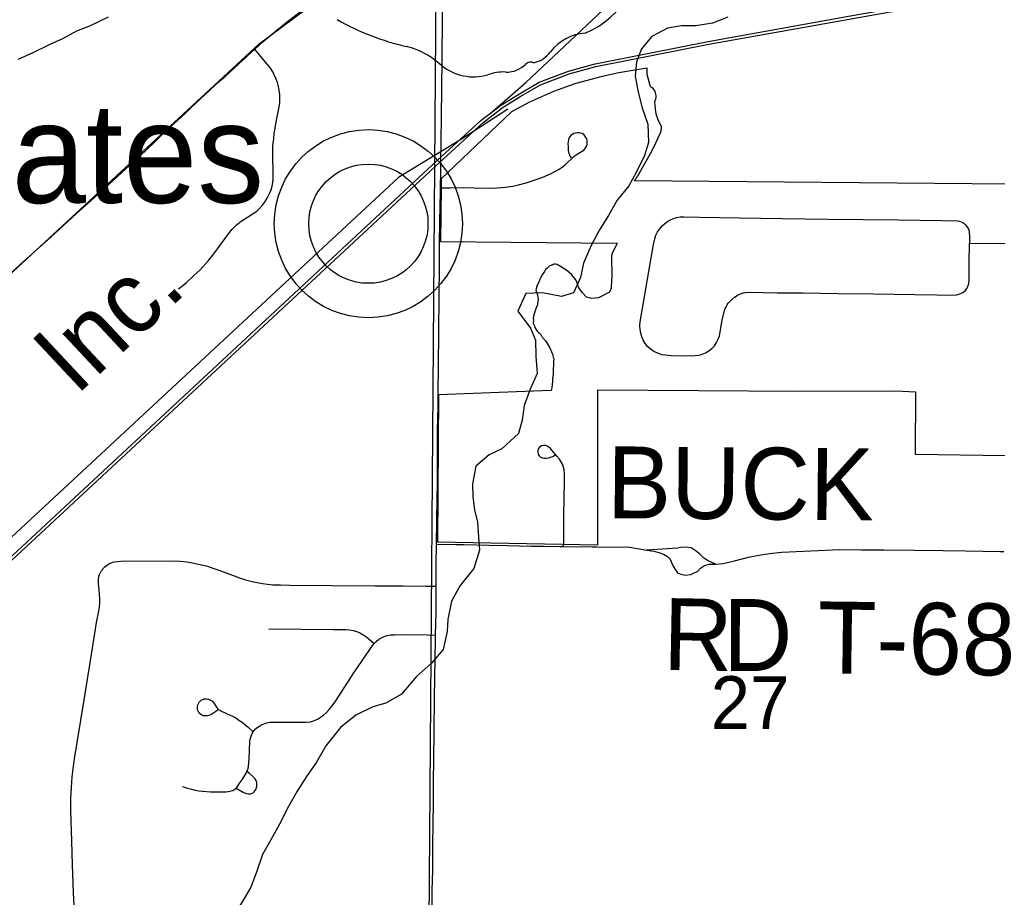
# Model space of a CAD drawing. Extents: x 0 to 34, y 0 to 22.
# Drawn here: x 5.674 to 6.448, y 19.121 to 19.815 of the extents above; entities that cross this region are included whole.
import ezdxf

# ---------------------------------------------------------------- set-up
doc = ezdxf.new("R2010")
doc.units = 0
for name, color, linetype in [('GM_X_City_Street', 7, 'Continuous'), ('GM_X_Corporation', 7, 'Continuous'), ('GM_X_Major_River', 7, 'Continuous'), ('GM_X_Minor_River', 7, 'Continuous'), ('GM_X_Rail_Line', 7, 'Continuous'), ('GM_X_Rail_Line_Text', 7, 'Continuous'), ('GM_X_Section_Text', 7, 'Continuous'), ('GM_X_State_Route', 7, 'Continuous'), ('GM_X_State_Shield', 7, 'Continuous'), ('GM_X_Township_Road', 7, 'Continuous'), ('GM_X_Township_Road_Text', 7, 'Continuous'), ('GM_X_Unincorporated', 7, 'Continuous'), ('GM_X_Unincorporated_Location', 7, 'Continuous'), ('GM_X_Unincorporated_Text', 7, 'Continuous')]:
    doc.layers.add(name, color=color, linetype=linetype)

msp = doc.modelspace()

# ---------------------------------------------------------------- linework, layer by layer
at = {"layer": 'GM_X_City_Street'}
for points in [[(6.0071, 19.68221), (6.01468, 19.68223), (6.02558, 19.68226), (6.03339, 19.68224), (6.04583, 19.68197), (6.052, 19.68215), (6.05816, 19.68266), (6.06428, 19.68351), (6.0688, 19.68441), (6.07476, 19.68603), (6.0821, 19.68847), (6.08813, 19.69067), (6.09451, 19.69333), (6.10088, 19.69696), (6.10327, 19.69856), (6.10576, 19.70044), (6.11251, 19.70691), (6.11378, 19.70795), (6.11515, 19.70885), (6.11923, 19.71112), (6.12039, 19.71197), (6.12138, 19.71295), (6.12218, 19.71408), (6.12277, 19.71533), (6.12313, 19.71666), (6.12324, 19.71804), (6.12311, 19.71942), (6.12273, 19.72077), (6.12214, 19.72205), (6.12135, 19.72322), (6.1204, 19.72421), (6.11929, 19.72497), (6.11805, 19.72541), (6.1167, 19.72557), (6.11522, 19.72556), (6.11378, 19.72539), (6.11246, 19.72502), (6.11125, 19.72441), (6.11021, 19.72357), (6.10933, 19.72252), (6.10867, 19.72131), (6.10824, 19.71998), (6.10805, 19.71858), (6.10789, 19.71681), (6.10796, 19.71477), (6.10806, 19.71307), (6.10818, 19.71169), (6.10864, 19.70936), (6.10903, 19.70818), (6.10965, 19.70685), (6.11039, 19.70579)], [(6.1755, 19.55305), (6.17305, 19.55475), (6.17087, 19.55676), (6.169, 19.55905), (6.1675, 19.56161), (6.16635, 19.56437), (6.16554, 19.56725), (6.16502, 19.5702), (6.16489, 19.57318), (6.16512, 19.57617), (6.16908, 19.59907), (6.17185, 19.61597), (6.17562, 19.63735), (6.1766, 19.6418), (6.17753, 19.64464), (6.1788, 19.64729), (6.18048, 19.64977), (6.18244, 19.65205), (6.18574, 19.65509)], [(6.18574, 19.65509), (6.18819, 19.65657), (6.19094, 19.65773), (6.19381, 19.65858), (6.19678, 19.65908), (6.19981, 19.65927), (6.21219, 19.65903), (6.24336, 19.65837), (6.27762, 19.65796), (6.31344, 19.65744), (6.36951, 19.65671), (6.40377, 19.65629), (6.41616, 19.65593), (6.41759, 19.65572), (6.41895, 19.65533), (6.42021, 19.65475), (6.42137, 19.65396), (6.4224, 19.65299), (6.4233, 19.65187), (6.42406, 19.65064), (6.4247, 19.64932), (6.42523, 19.64794), (6.42567, 19.64279), (6.42552, 19.6381), (6.46088, 19.63839)], [(6.1755, 19.55305), (6.17915, 19.55129), (6.18202, 19.55045), (6.185, 19.54996), (6.18959, 19.54958), (6.19889, 19.54938), (6.2082, 19.5495), (6.2112, 19.54978), (6.21264, 19.55008), (6.21405, 19.5505), (6.21674, 19.55172), (6.2193, 19.5533), (6.22169, 19.55514), (6.22375, 19.55726), (6.22547, 19.55969), (6.22679, 19.56235), (6.22767, 19.56517), (6.22996, 19.57741), (6.23177, 19.58505), (6.23231, 19.58662), (6.23301, 19.58812), (6.23382, 19.58953), (6.23475, 19.59088), (6.23691, 19.59332), (6.23938, 19.59541), (6.24209, 19.59718), (6.24355, 19.59793), (6.24507, 19.59855), (6.24665, 19.59902), (6.24828, 19.59932), (6.2515, 19.59952), (6.26245, 19.59931), (6.27333, 19.599), (6.29358, 19.59896), (6.32162, 19.59856), (6.34966, 19.59826), (6.38239, 19.59773), (6.3997, 19.59745), (6.41039, 19.59729), (6.41493, 19.59752), (6.41638, 19.59778), (6.41778, 19.59819), (6.41913, 19.59873), (6.4204, 19.59943), (6.42154, 19.60028), (6.42255, 19.60128), (6.42339, 19.60241), (6.42407, 19.60366), (6.42459, 19.605), (6.42493, 19.6064), (6.42517, 19.60937), (6.42534, 19.62305), (6.42552, 19.6381)], [(6.10452, 19.3985), (6.10454, 19.40149), (6.10457, 19.40692), (6.10465, 19.42299), (6.10512, 19.44961), (6.10512, 19.45587), (6.10481, 19.45899), (6.10412, 19.46204), (6.10357, 19.46351), (6.10288, 19.46491), (6.10206, 19.46623), (6.1011, 19.46748), (6.09905, 19.46984), (6.09401, 19.47586), (6.09288, 19.47695), (6.09159, 19.4778), (6.09012, 19.47829), (6.08856, 19.47836), (6.08704, 19.47801), (6.08568, 19.47723), (6.08464, 19.47609), (6.08404, 19.47467), (6.08397, 19.47311), (6.08436, 19.47159), (6.08517, 19.47025), (6.08632, 19.4692), (6.08775, 19.46857), (6.08929, 19.46833), (6.09086, 19.46828), (6.0924, 19.46851), (6.09424, 19.469), (6.09585, 19.46965), (6.09762, 19.47071)]]:
    msp.add_lwpolyline(points, dxfattribs=at)
at = {"layer": 'GM_X_Corporation'}
msp.add_lwpolyline([(6.51238, 19.90438), (6.50454, 18.87812), (5.99643, 18.88937), (6.00425, 19.91036)], close=True, dxfattribs=at)
msp.add_lwpolyline([(6.4572, 19.685), (6.16051, 19.68759), (6.16083, 19.68838), (6.16145, 19.68903), (6.16175, 19.6894), (6.16244, 19.69072), (6.16314, 19.69161), (6.17329, 19.70935), (6.17613, 19.71492), (6.18098, 19.72499), (6.18139, 19.72653), (6.18177, 19.72724), (6.18187, 19.72915), (6.18184, 19.73042), (6.17932, 19.73595), (6.17798, 19.73953), (6.17736, 19.74213), (6.17671, 19.75011), (6.17706, 19.75174), (6.17738, 19.75225), (6.17763, 19.75317), (6.17776, 19.75511), (6.17678, 19.75844), (6.17615, 19.7597), (6.17534, 19.7606), (6.17406, 19.76149), (6.17323, 19.76235), (6.17283, 19.76309), (6.17048, 19.77176), (6.17048, 19.77666), (6.14818, 19.77306), (6.13503, 19.77029), (6.11428, 19.76453), (6.09655, 19.75819), (6.07741, 19.74977), (6.06327, 19.74233), (6.00764, 19.68915), (6.00757, 19.68273), (6.00709, 19.63957), (6.11861, 19.63869), (6.14691, 19.63846), (6.14422, 19.63279), (6.14273, 19.63003), (6.14234, 19.62809), (6.14271, 19.61149), (6.14234, 19.60905), (6.14219, 19.60275), (6.14065, 19.5995), (6.132, 19.5951), (6.12683, 19.59467), (6.12469, 19.59507), (6.12253, 19.59568), (6.11931, 19.59901), (6.11805, 19.60102), (6.11634, 19.60365), (6.1158, 19.60555), (6.11414, 19.60936), (6.11108, 19.61343), (6.10671, 19.61707), (6.09926, 19.62158), (6.09812, 19.62188), (6.09682, 19.62172), (6.09574, 19.62125), (6.09528, 19.62124), (6.09504, 19.62101), (6.09348, 19.62039), (6.09317, 19.62018), (6.09266, 19.61962), (6.09112, 19.61825), (6.09026, 19.61746), (6.08929, 19.61609), (6.08749, 19.61331), (6.08674, 19.61202), (6.0862, 19.61082), (6.08597, 19.61037), (6.08578, 19.60964), (6.08477, 19.6074), (6.08368, 19.60519), (6.08348, 19.60501), (6.08313, 19.60402), (6.08294, 19.6031), (6.08275, 19.60216), (6.08263, 19.60124), (6.08266, 19.60066), (6.08283, 19.60011), (6.08358, 19.59836), (6.08385, 19.59669), (6.08434, 19.59466), (6.08439, 19.59429), (6.08422, 19.59201), (6.08393, 19.59016), (6.08375, 19.5896), (6.08273, 19.58735), (6.08095, 19.58178), (6.08049, 19.57917), (6.08056, 19.57784), (6.08052, 19.57519), (6.08091, 19.57393), (6.08137, 19.57308), (6.08163, 19.57207), (6.08172, 19.5718), (6.08298, 19.56969), (6.08388, 19.56848), (6.08452, 19.56779), (6.08544, 19.56712), (6.08587, 19.56674), (6.08634, 19.56613), (6.08715, 19.56465), (6.08749, 19.56419), (6.08772, 19.56388), (6.08798, 19.5636), (6.08874, 19.56271), (6.08905, 19.56228), (6.08931, 19.56201), (6.08948, 19.56189), (6.08962, 19.56176), (6.09013, 19.56111), (6.09077, 19.56028), (6.0913, 19.55947), (6.09163, 19.5588), (6.0917, 19.55862), (6.09186, 19.55838), (6.09251, 19.55756), (6.093, 19.55675), (6.09414, 19.55416), (6.09561, 19.55067), (6.0959, 19.54938), (6.09633, 19.54832), (6.09645, 19.54757), (6.09668, 19.54674), (6.09645, 19.54524), (6.09631, 19.5352), (6.09599, 19.53266), (6.09581, 19.53125), (6.09567, 19.52898), (6.09524, 19.52407), (6.09453, 19.52177), (6.00553, 19.51842), (6.00473, 19.40219), (6.13146, 19.39982), (6.13153, 19.52233), (6.29046, 19.52131), (6.36736, 19.52147), (6.38296, 19.52085), (6.38257, 19.47159), (6.4539, 19.47047)], dxfattribs=at)
at = {"layer": 'GM_X_Major_River'}
msp.add_lwpolyline([(5.67296, 19.78399), (5.68429, 19.78888), (5.69843, 19.79584), (5.70831, 19.80027), (5.71934, 19.80621), (5.7296, 19.81026), (5.74459, 19.81733)], dxfattribs=at)
at = {"layer": 'GM_X_Minor_River'}
for points in [[(6.2345, 19.81701), (6.22235, 19.81223), (6.2091, 19.81012), (6.19777, 19.81026), (6.18679, 19.8085), (6.17423, 19.80182), (6.16617, 19.79206), (6.16226, 19.78186), (6.16098, 19.77011), (6.16383, 19.75679), (6.1667, 19.74537), (6.17106, 19.73242), (6.17163, 19.71799), (6.16847, 19.70778), (6.16187, 19.6942), (6.15607, 19.68365), (6.14686, 19.67238), (6.1399, 19.66032), (6.13295, 19.64902), (6.12637, 19.63658), (6.12014, 19.62262), (6.11772, 19.61126), (6.11228, 19.59919), (6.1028, 19.59627), (6.08772, 19.59912), (6.07449, 19.59852), (6.06826, 19.58456), (6.07829, 19.57115), (6.08232, 19.56161), (6.08254, 19.54909), (6.08349, 19.53541), (6.07804, 19.52295), (6.07334, 19.51011), (6.07167, 19.49837), (6.06889, 19.48778), (6.05551, 19.4758), (6.04563, 19.47099), (6.03493, 19.46202), (6.03248, 19.44801), (6.03273, 19.43775), (6.0341, 19.42749), (6.03624, 19.4176), (6.03722, 19.40582), (6.03784, 19.39556), (6.0335, 19.3812), (6.02275, 19.36767), (6.01578, 19.35523), (6.01295, 19.34085), (6.01245, 19.33137), (6.00924, 19.31698), (6.00003, 19.30609), (5.98819, 19.29562), (5.97629, 19.28172), (5.96373, 19.27467), (5.9535, 19.27176), (5.94019, 19.2651), (5.92797, 19.25538), (5.91645, 19.24073), (5.9091, 19.22792), (5.90102, 19.21663), (5.89369, 19.20496), (5.88674, 19.1929), (5.87975, 19.17894)], [(5.87975, 19.17894), (5.87279, 19.16651), (5.86622, 19.15483), (5.8615, 19.14084), (5.85719, 19.12913), (5.84986, 19.11708), (5.84023, 19.10278), (5.82763, 19.09231), (5.81088, 19.08303), (5.79986, 19.07786), (5.78959, 19.07267), (5.77894, 19.06673), (5.76907, 19.06344), (5.75694, 19.0598), (5.74441, 19.0554), (5.73301, 19.04985), (5.72349, 19.04466), (5.71465, 19.033), (5.70465, 19.01871)]]:
    msp.add_lwpolyline(points, dxfattribs=at)
at = {"layer": 'GM_X_Rail_Line'}
msp.add_line((6.06042, 19.74445), (6.02958, 19.7244), dxfattribs=at)
for points in [[(4.78429, 18.80343), (5.20213, 19.1854), (5.56639, 19.5213), (5.86365, 19.79605), (5.94571, 19.8572), (6.00433, 19.89992), (6.77122, 20.65037), (6.78738, 20.68459), (6.84059, 20.85665), (6.88559, 20.9)], [(6.04603, 19.74071), (6.07463, 19.76544), (6.4431, 20.11209)], [(6.0391, 19.7355), (6.05467, 19.74722), (6.06953, 19.75648), (6.08509, 19.76562), (6.10827, 19.77436), (6.12947, 19.7803), (6.21883, 19.79798), (6.32982, 19.81787), (6.51134, 19.85016), (6.6502, 19.87532), (6.69488, 19.88232), (6.73475, 19.88693), (6.77076, 19.89004), (6.82866, 19.89259), (6.91252, 19.89191), (7.71042, 19.87786)], [(6.04051, 19.73365), (6.056, 19.74531), (6.07074, 19.7545), (6.0861, 19.76352), (6.109, 19.77215), (6.13002, 19.77804), (6.21926, 19.7957), (6.33023, 19.81559), (6.51176, 19.84787), (6.65059, 19.87303), (6.69519, 19.88002), (6.73499, 19.88462), (6.77091, 19.88772), (6.82871, 19.89027), (6.91249, 19.88959), (7.71038, 19.87554)], [(4.0369, 17.87629), (4.0405, 17.87963), (4.10582, 17.94022), (4.26502, 18.087), (4.55609, 18.35576), (4.76707, 18.55171), (4.9213, 18.69505), (5.34845, 19.09084), (6.00629, 19.70228), (6.04051, 19.73365)], [(4.26344, 18.0887), (4.5545, 18.35746), (4.76549, 18.55341), (4.91971, 18.69674), (5.34686, 19.09254), (6.00471, 19.70399), (6.03893, 19.73535)], [(6.02958, 19.7244), (6.02241, 19.71974), (5.97395, 19.69027), (5.5555, 19.30184), (5.32439, 19.08907), (5.10249, 18.8805), (5.04303, 18.84113), (4.98191, 18.81432), (4.92078, 18.80008), (4.84793, 18.79757), (4.78429, 18.80343)]]:
    msp.add_lwpolyline(points, dxfattribs=at)
at = {"layer": 'GM_X_State_Route'}
msp.add_lwpolyline([(5.66772, 19.61524), (5.67694, 19.62362), (5.69914, 19.6435), (5.71904, 19.66149), (5.73343, 19.67439), (5.74491, 19.68501), (5.75824, 19.69703), (5.77376, 19.71133), (5.78227, 19.71958), (5.78831, 19.72555), (5.79332, 19.73003), (5.80512, 19.74099), (5.80958, 19.74533), (5.82087, 19.756), (5.83239, 19.76635), (5.83702, 19.77046), (5.84391, 19.77672), (5.85077, 19.78303), (5.85761, 19.78938), (5.86024, 19.79178), (5.8668, 19.79776), (5.87624, 19.80587), (5.88609, 19.81358), (5.89713, 19.82218)], dxfattribs=at)
at = {"layer": 'GM_X_State_Shield'}
for centre, radius, start, end in [((6.09506, 19.86925), 0.06994, 292.30889, 8.98584), ((6.02504, 19.99079), 0.20192, 240.41292, 257.1985), ((6.12455, 19.76635), 0.0383, 94.40312, 142.57675), ((5.96484, 19.73263), 0.06318, 47.18416, 75.83597), ((6.07602, 19.80314), 0.0226, 282.87319, 323.27711), ((6.03317, 19.81), 0.04009, 230.70037, 286.29184), ((6.05926, 19.79501), 0.02136, 268.77702, 315.54927), ((6.07859, 19.77563), 0.00601, 65.75173, 132.64842), ((6.05633, 19.74081), 0.03294, 85.69512, 111.20995)]:
    msp.add_arc(centre, radius, start, end, dxfattribs=at)
at = {"layer": 'GM_X_Township_Road'}
msp.add_line((6.0071, 19.68221), (6.00741, 19.69531), dxfattribs=at)
for points in [[(6.00741, 19.69531), (6.00741, 19.70251), (6.00767, 19.71953), (6.00784, 19.73795), (6.00843, 19.78409), (6.00859, 19.81602), (6.00853, 19.8374), (6.0091, 19.86146), (6.00944, 19.88418), (6.00927, 19.88778), (6.00847, 19.89418), (6.00803, 19.89681), (6.00649, 19.90319)], [(5.79986, 19.60215), (5.80585, 19.60712), (5.81204, 19.61275), (5.817, 19.61734), (5.82346, 19.62456), (5.82778, 19.63), (5.8393, 19.64565), (5.8423, 19.64931), (5.84548, 19.6525), (5.84951, 19.65568), (5.85448, 19.65906), (5.86169, 19.66375), (5.86366, 19.66553), (5.866, 19.66825), (5.86778, 19.6705), (5.86918, 19.67257), (5.87059, 19.675), (5.87218, 19.67819), (5.87312, 19.68044), (5.87396, 19.68335), (5.87452, 19.68625), (5.8748, 19.68925), (5.8748, 19.6929), (5.8747, 19.69722), (5.87452, 19.70434), (5.87442, 19.70931), (5.8746, 19.71521), (5.87516, 19.72093), (5.87544, 19.72515), (5.87619, 19.72936), (5.87694, 19.73283), (5.87823, 19.7397), (5.87956, 19.74614), (5.87993, 19.74924), (5.88002, 19.75252), (5.87993, 19.7557), (5.87955, 19.75927), (5.87899, 19.76236), (5.87814, 19.76545), (5.87693, 19.76854), (5.87561, 19.77136), (5.87439, 19.77398), (5.87261, 19.77679), (5.86379, 19.78747), (5.86024, 19.79178)], [(6.00641, 19.63808), (6.00663, 19.65571), (6.00702, 19.679), (6.0071, 19.68221)], [(6.00535, 19.51719), (6.00544, 19.54426), (6.00578, 19.56496), (6.00603, 19.59882), (6.00641, 19.6171), (6.00638, 19.6265), (6.00641, 19.63808)], [(6.00398, 19.40044), (6.00423, 19.41849), (6.00448, 19.4363), (6.00474, 19.44875), (6.00473, 19.47603), (6.00472, 19.48848), (6.00496, 19.50135), (6.00516, 19.50755), (6.00535, 19.51719)], [(6.00362, 19.36707), (6.0037, 19.38386), (6.00398, 19.40044)], [(6.00398, 19.40044), (6.01951, 19.40008), (6.0253, 19.40009), (6.04568, 19.39962), (6.05981, 19.39929), (6.07874, 19.39885), (6.08869, 19.39878), (6.10177, 19.39853), (6.10452, 19.3985)], [(6.10452, 19.3985), (6.1274, 19.39822), (6.13086, 19.39817)], [(6.13086, 19.39817), (6.15692, 19.39792), (6.17042, 19.39569)], [(6.22472, 19.38452), (6.21879, 19.38722), (6.21542, 19.38922), (6.21214, 19.39232), (6.2094, 19.39488), (6.20539, 19.39743), (6.20136, 19.39797), (6.1969, 19.39776), (6.19468, 19.39709), (6.17042, 19.39569)], [(6.17042, 19.39569), (6.17577, 19.39475), (6.17987, 19.3938), (6.18349, 19.39238), (6.18679, 19.39065), (6.18868, 19.38845), (6.18994, 19.38578), (6.1912, 19.38294), (6.19261, 19.38027), (6.1945, 19.37775), (6.19718, 19.37665), (6.20064, 19.37586), (6.2052, 19.37633), (6.21055, 19.37901), (6.21276, 19.38137), (6.2159, 19.38341), (6.21952, 19.38452), (6.22472, 19.38452)], [(6.22472, 19.38452), (6.2307, 19.38499), (6.23967, 19.38703), (6.25068, 19.39002), (6.25902, 19.39176), (6.26736, 19.39301), (6.27712, 19.39396), (6.32288, 19.39615), (6.3404, 19.39594), (6.35783, 19.39596), (6.38212, 19.39558), (6.40433, 19.39524), (6.42251, 19.39495), (6.44985, 19.39462), (6.45167, 19.3946), (6.45268, 19.39458)], [(5.71781, 19.10312), (5.71687, 19.12496), (5.7161, 19.14679), (5.71546, 19.16548), (5.71466, 19.18977), (5.71458, 19.19921), (5.7151, 19.20791), (5.71577, 19.21624), (5.71644, 19.22261), (5.71756, 19.23063), (5.71958, 19.24345), (5.72542, 19.27877), (5.73095, 19.3132), (5.73496, 19.33828), (5.73693, 19.34741), (5.73732, 19.35058), (5.73752, 19.35378), (5.73753, 19.35697), (5.73735, 19.36016), (5.73707, 19.36441), (5.7367, 19.36883), (5.7367, 19.37295), (5.73678, 19.37406), (5.73692, 19.3749), (5.73735, 19.37628), (5.73793, 19.37747), (5.73877, 19.37891), (5.73944, 19.37989), (5.74007, 19.38076), (5.74077, 19.38162), (5.74152, 19.38232), (5.74269, 19.38331), (5.74384, 19.38417), (5.74485, 19.3848), (5.74585, 19.38527), (5.74689, 19.38563), (5.74791, 19.38597), (5.74907, 19.38623), (5.75147, 19.38661), (5.75416, 19.38676), (5.79465, 19.38715), (5.80095, 19.38685), (5.80643, 19.38633), (5.81085, 19.38566), (5.8158, 19.38461), (5.81947, 19.38372), (5.82285, 19.38281), (5.82705, 19.38147), (5.8317, 19.37989), (5.84805, 19.37368), (5.85284, 19.3721), (5.85802, 19.37076), (5.86207, 19.36993), (5.86619, 19.36919), (5.87024, 19.36867), (5.87459, 19.36829), (5.88051, 19.36807), (5.88794, 19.36799), (5.92078, 19.36763), (5.95542, 19.36727), (5.97761, 19.36729), (5.99561, 19.36714), (6.00362, 19.36707)], [(6.00313, 19.32841), (6.00359, 19.34653), (6.00358, 19.35792), (6.00362, 19.36707)], [(5.87133, 19.33347), (5.92262, 19.33289), (5.93259, 19.33283), (5.93509, 19.33265), (5.93808, 19.33209), (5.94099, 19.33123), (5.94378, 19.33001), (5.94643, 19.32846), (5.94879, 19.32669), (5.95074, 19.32511), (5.95464, 19.32189)], [(5.95464, 19.32189), (5.95629, 19.32339), (5.95834, 19.32513), (5.9603, 19.32637), (5.96251, 19.32734), (5.96483, 19.32805), (5.96757, 19.3285), (5.97059, 19.32868), (5.97937, 19.32877), (5.9965, 19.32851), (6.00313, 19.32841)], [(5.99811, 19.00567), (5.99814, 19.00836), (5.99822, 19.01153), (5.99853, 19.02359), (5.99912, 19.03954), (5.99963, 19.06457), (5.99976, 19.08019), (6.00048, 19.10554), (6.00063, 19.12675), (6.00101, 19.14226), (6.00093, 19.15724), (6.00105, 19.1628), (6.00137, 19.17815), (6.0015, 19.19689), (6.00162, 19.21132), (6.00203, 19.25148), (6.00242, 19.27928), (6.00305, 19.325), (6.00313, 19.32841)], [(5.85901, 19.25203), (5.86061, 19.25409), (5.86172, 19.25515), (5.86282, 19.25594), (5.86416, 19.25677), (5.86539, 19.25741), (5.86672, 19.25801), (5.86813, 19.25851), (5.86976, 19.25896), (5.87222, 19.25944), (5.87498, 19.25961), (5.89725, 19.25953), (5.90079, 19.25953), (5.90425, 19.25989), (5.90736, 19.26078), (5.90975, 19.26185), (5.91224, 19.26344), (5.91454, 19.26504), (5.91685, 19.26717), (5.91907, 19.26948), (5.92119, 19.27223), (5.92385, 19.27569), (5.93919, 19.29948), (5.95365, 19.32051), (5.95464, 19.32189)], [(5.83085, 19.26899), (5.82628, 19.26577), (5.82523, 19.26526), (5.82396, 19.26485), (5.82272, 19.2646), (5.82133, 19.26451), (5.81968, 19.26469), (5.81838, 19.26517), (5.8172, 19.26587), (5.81628, 19.26672), (5.81562, 19.26764), (5.81514, 19.26869), (5.81488, 19.26986), (5.81485, 19.27082), (5.81501, 19.27224), (5.81526, 19.27329), (5.81555, 19.27421), (5.81612, 19.27526), (5.81698, 19.27624), (5.81783, 19.27698), (5.81898, 19.27758), (5.81993, 19.2779), (5.82091, 19.27802), (5.82225, 19.27806), (5.82358, 19.27786), (5.82485, 19.27732), (5.82581, 19.27675), (5.82663, 19.27613), (5.8274, 19.2753), (5.82817, 19.27426), (5.82932, 19.27225), (5.8299, 19.2713), (5.83069, 19.27035), (5.83145, 19.26971), (5.83395, 19.26825), (5.83777, 19.26638), (5.84244, 19.2644), (5.84509, 19.26291), (5.84765, 19.26127), (5.85011, 19.25945), (5.85486, 19.25549), (5.85901, 19.25203)], [(5.85404, 19.22048), (5.85457, 19.22184), (5.85496, 19.2233), (5.8552, 19.22447), (5.85564, 19.2305), (5.85626, 19.24434), (5.85656, 19.24617), (5.85705, 19.24782), (5.8582, 19.25057), (5.85901, 19.25203)], [(5.84554, 19.20743), (5.84652, 19.20876), (5.84847, 19.21151), (5.84997, 19.21382), (5.85175, 19.21666), (5.85343, 19.21932), (5.85404, 19.22048)], [(5.84554, 19.20743), (5.85037, 19.20438), (5.85205, 19.20356), (5.85363, 19.2031), (5.85533, 19.20293), (5.85652, 19.203), (5.8577, 19.20326), (5.85879, 19.20375), (5.85935, 19.20418), (5.85983, 19.20459), (5.86053, 19.20557), (5.86122, 19.20695), (5.86175, 19.20873), (5.86195, 19.21037), (5.86188, 19.21165), (5.86152, 19.21297), (5.86089, 19.21425), (5.86026, 19.21514), (5.85868, 19.21672), (5.85601, 19.21906), (5.85404, 19.22048)], [(5.80295, 19.20865), (5.80694, 19.20732), (5.81018, 19.20655), (5.8131, 19.20584), (5.81606, 19.20528), (5.81906, 19.20487), (5.82512, 19.2044), (5.83392, 19.20441), (5.83764, 19.2045), (5.83905, 19.20469), (5.84048, 19.20494), (5.8416, 19.20523), (5.84271, 19.2056), (5.84369, 19.20611), (5.8443, 19.20645), (5.84554, 19.20743)]]:
    msp.add_lwpolyline(points, dxfattribs=at)
at = {"layer": 'GM_X_Unincorporated'}
for radius in [0.0744, 0.04716]:
    msp.add_circle((5.95004, 19.65377), radius, dxfattribs=at)
at = {"layer": 'GM_X_Unincorporated_Location'}
msp.add_line((5.95004, 19.65377), (5.95004, 19.65377), dxfattribs=at)

# ---------------------------------------------------------------- texts
at = {"layer": 'GM_X_Rail_Line_Text'}
msp.add_text('Inc.', height=0.056629, rotation=43.09193, dxfattribs=at).set_placement((5.7186, 19.51697))
at = {"layer": 'GM_X_Section_Text'}
msp.add_text('27', height=0.041856, rotation=0.00001, dxfattribs=at).set_placement((6.22082, 19.25404))
at = {"layer": 'GM_X_Township_Road_Text'}
for s, height, rotation, p in [('BUCK', 0.056818, 359.50718, (6.13861, 19.42094)), ('R', 0.05682, 358.93837, (6.18279, 19.30098)), ('D', 0.05682, 359.95689, (6.23053, 19.3001)), ('T-68', 0.056818, 359.29663, (6.30527, 19.29829))]:
    msp.add_text(s, height=height, rotation=rotation, dxfattribs=at).set_placement(p)
at = {"layer": 'GM_X_Unincorporated_Text'}
msp.add_text('Bates', height=0.078977, rotation=0.00001, dxfattribs=at).set_placement((5.59749, 19.67019))

doc.saveas('drawing.dxf')
